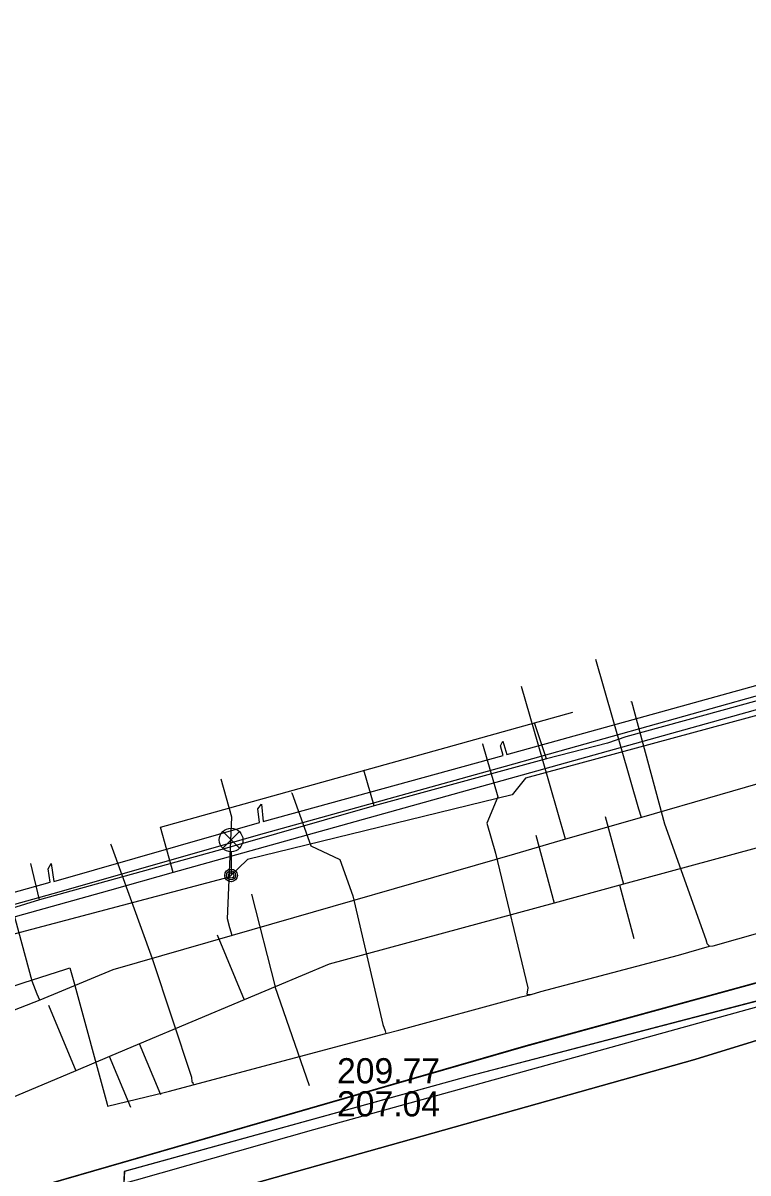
# Model space of a CAD drawing. Extents: x -595540 to -593988, y -1160850 to -1159202.
# Drawn here: x -595477.48 to -595454.45, y -1160206.4 to -1160169.86 of the extents above; entities that cross this region are included whole.
import ezdxf

# ---------------------------------------------------------------- set-up
doc = ezdxf.new("R2010")
doc.units = 0
for name, color, linetype in [('BVK-JEDNOTNA_popisy', 7, 'Continuous'), ('BVK-JEDNOTNA_trasa sítě', 7, 'Continuous'), ('BVK-VODOVOD_trasa sítě', 7, 'Continuous'), ('CETIN_kabel podzemní', 7, 'Continuous'), ('DESTOVA_trasa neprovozované sítě', 7, 'Continuous'), ('DSP-SDEL-VODAFONE_kabel', 7, 'Continuous'), ('EON-NN_kabel', 7, 'Continuous'), ('EON-SDEL_kabel', 7, 'Continuous'), ('INNOGY-STL_trasa sítě', 7, 'Continuous'), ('JEDNOTNA_trasa neprovozované sítě', 7, 'Continuous'), ('QUANTCOM_kabel', 7, 'Continuous'), ('TSB_kabel VO', 7, 'Continuous'), ('TSB_lampy VO', 7, 'Continuous')]:
    doc.layers.add(name, color=color, linetype=linetype)

msp = doc.modelspace()

# ---------------------------------------------------------------- linework, layer by layer
at = {"layer": 'BVK-JEDNOTNA_popisy'}
msp.add_line((-595467.506, -1160203.672), (-595467.506, -1160203.672), dxfattribs=at)
at = {"layer": 'BVK-JEDNOTNA_trasa sítě'}
for points in [[(-595429.502, -1160189.373), (-595434.244, -1160190.66), (-595449.231, -1160194.729), (-595450.1, -1160194.965), (-595458.409, -1160197.221), (-595458.525, -1160197.252), (-595460.609, -1160197.818), (-595467.756, -1160199.758)], [(-595467.756, -1160199.758), (-595469.474, -1160200.481), (-595470.451, -1160200.893), (-595473.778, -1160202.294), (-595474.727, -1160202.693), (-595475.796, -1160203.144), (-595482.321, -1160205.891), (-595489.004, -1160208.705), (-595495.961, -1160211.635), (-595502.779, -1160214.506)]]:
    msp.add_lwpolyline(points, dxfattribs=at)
at = {"layer": 'BVK-VODOVOD_trasa sítě'}
for points in [[(-595433.371, -1160188.474), (-595450.372, -1160192.941), (-595457.841, -1160195.098), (-595460.25, -1160195.793), (-595461.873, -1160196.262), (-595470.837, -1160198.85), (-595474.622, -1160199.943), (-595476.949, -1160200.901), (-595479.453, -1160201.882), (-595489.375, -1160205.387), (-595494.55, -1160207.296), (-595496.292, -1160208.601), (-595507.397, -1160216.918), (-595511.24, -1160217.318)], [(-595457.841, -1160195.098), (-595457.916, -1160194.84), (-595459.291, -1160190.076)], [(-595460.25, -1160195.793), (-595460.985, -1160193.249), (-595461.652, -1160190.937)], [(-595470.837, -1160198.85), (-595470.906, -1160198.611), (-595470.989, -1160198.322), (-595470.847, -1160195.087), (-595471.184, -1160193.884)], [(-595476.949, -1160200.901), (-595477.026, -1160200.714), (-595477.192, -1160200.305), (-595478.434, -1160195.711)]]:
    msp.add_lwpolyline(points, dxfattribs=at)
at = {"layer": 'CETIN_kabel podzemní'}
for points in [[(-595436.82, -1160185.01), (-595436.68, -1160186.27), (-595437.8, -1160187.11), (-595448.91, -1160190.21), (-595472.71, -1160196.85)], [(-595473.11, -1160195.41), (-595460.02, -1160191.75)], [(-595472.71, -1160196.85), (-595473.11, -1160195.41)], [(-595472.71, -1160196.85), (-595474.73, -1160197.42)], [(-595474.73, -1160197.42), (-595503.07, -1160205.33)], [(-595446.81, -1160199.08), (-595468.25, -1160205.02), (-595473.88, -1160206.62), (-595474.28, -1160206.73)], [(-595446.81, -1160199.08), (-595453.59, -1160200.78), (-595463.31, -1160203.32), (-595474.26, -1160206.35), (-595474.28, -1160206.73)]]:
    msp.add_lwpolyline(points, dxfattribs=at)
at = {"layer": 'DESTOVA_trasa neprovozované sítě'}
for p in [(-595470.22, -1160197.54), (-595468.38, -1160203.63)]:
    msp.add_line(p, (-595469.474, -1160200.481), dxfattribs=at)
at = {"layer": 'DSP-SDEL-VODAFONE_kabel'}
for p, q in [((-595449.44, -1160190.1), (-595455.28, -1160191.7)), ((-595455.28, -1160191.7), (-595458.33, -1160192.54)), ((-595460.85, -1160193.24), (-595461.23, -1160192.09)), ((-595458.92, -1160192.74), (-595460.85, -1160193.24)), ((-595458.33, -1160192.54), (-595458.92, -1160192.74)), ((-595460.85, -1160193.24), (-595466.33, -1160194.73)), ((-595466.33, -1160194.73), (-595466.65, -1160193.6)), ((-595466.33, -1160194.73), (-595471.02, -1160196.08)), ((-595471.02, -1160196.08), (-595476.95, -1160197.72)), ((-595476.95, -1160197.72), (-595477.23, -1160196.56)), ((-595476.95, -1160197.72), (-595478.87, -1160198.3))]:
    msp.add_line(p, q, dxfattribs=at)
for points in [[(-595413.104, -1160211.94), (-595415.781, -1160206.019), (-595417.304, -1160202.745), (-595418.846, -1160199.575), (-595420.945, -1160195.335), (-595421.972, -1160193.286), (-595422.732, -1160193.55), (-595430.168, -1160195.953), (-595432.695, -1160196.302), (-595433.235, -1160196.434), (-595433.698, -1160196.516), (-595435.229, -1160196.972), (-595435.74, -1160197.085), (-595436.166, -1160197.235), (-595436.651, -1160197.368), (-595437.606, -1160197.665), (-595450.678, -1160201.105), (-595456.146, -1160202.789), (-595473.119, -1160207.564)], [(-595473.119, -1160207.564), (-595456.146, -1160202.789), (-595450.678, -1160201.105), (-595437.606, -1160197.665), (-595436.651, -1160197.368), (-595436.166, -1160197.235), (-595435.74, -1160197.085), (-595435.229, -1160196.972), (-595433.698, -1160196.516), (-595433.235, -1160196.434), (-595432.695, -1160196.302), (-595430.168, -1160195.953), (-595422.732, -1160193.55)], [(-595473.119, -1160207.564), (-595456.146, -1160202.789), (-595450.678, -1160201.105), (-595437.606, -1160197.665), (-595436.651, -1160197.368), (-595436.166, -1160197.235), (-595435.74, -1160197.085), (-595435.229, -1160196.972), (-595433.698, -1160196.516), (-595433.235, -1160196.434), (-595432.695, -1160196.302), (-595430.168, -1160195.953), (-595422.732, -1160193.55)], [(-595428.8, -1160199.016), (-595429.894, -1160199.431), (-595431.092, -1160198.649), (-595434.259, -1160196.161), (-595435.098, -1160195.864), (-595444.353, -1160198.46), (-595453.588, -1160200.784), (-595463.313, -1160203.317), (-595474.262, -1160206.352), (-595474.287, -1160206.967), (-595473.746, -1160209.094), (-595473.527, -1160213.403), (-595471.041, -1160220.681)]]:
    msp.add_lwpolyline(points, dxfattribs=at)
at = {"layer": 'EON-NN_kabel'}
for points in [[(-595483.257, -1160199.008), (-595476.613, -1160197.16), (-595476.683, -1160196.728), (-595476.586, -1160196.559), (-595476.496, -1160197.133), (-595469.969, -1160195.261), (-595470.017, -1160194.822), (-595469.902, -1160194.676), (-595469.851, -1160195.227), (-595462.231, -1160193.13), (-595462.314, -1160192.819), (-595462.24, -1160192.672), (-595462.116, -1160193.097), (-595451.076, -1160190.039), (-595451.174, -1160189.666), (-595451.094, -1160189.509), (-595450.966, -1160189.991), (-595439.303, -1160186.706), (-595438.814, -1160188.314), (-595436.543, -1160195.46), (-595436.019, -1160197.889), (-595436.002, -1160198.414)], [(-595495.701, -1160250.262), (-595500.278, -1160233.753), (-595501.151, -1160230.603), (-595505.432, -1160214.583), (-595507.104, -1160207.458), (-595506.798, -1160206.888), (-595505.989, -1160206.57), (-595506.055, -1160206.463), (-595505.866, -1160206.422), (-595505.739, -1160206.394), (-595501.343, -1160205.41), (-595500.994, -1160204.257), (-595489.867, -1160201.187), (-595483.299, -1160199.405), (-595476.52, -1160197.518), (-595469.812, -1160195.596), (-595462.151, -1160193.471), (-595450.83, -1160190.291), (-595439.513, -1160187.038), (-595439.111, -1160188.297), (-595436.822, -1160195.513), (-595436.263, -1160198.081), (-595436.2, -1160198.473)]]:
    msp.add_lwpolyline(points, dxfattribs=at)
at = {"layer": 'EON-SDEL_kabel'}
msp.add_lwpolyline([(-595481, -1160207.991), (-595461.51, -1160202.361), (-595440.89, -1160196.711), (-595436.93, -1160185.301), (-595437.35, -1160184.671), (-595437.62, -1160184.061), (-595439.81, -1160179.531), (-595441.07, -1160177.061), (-595441.59, -1160176.011), (-595444.38, -1160170.151), (-595447.98, -1160162.891), (-595448.43, -1160161.911), (-595449.58, -1160159.381), (-595451.65, -1160155.171), (-595452.88, -1160152.441), (-595453.77, -1160150.781)], dxfattribs=at)
at = {"layer": 'INNOGY-STL_trasa sítě'}
for points in [[(-595458.17, -1160191.415), (-595458.158, -1160191.414), (-595457.105, -1160195.307), (-595455.797, -1160198.981), (-595455.767, -1160199.056), (-595455.764, -1160199.099), (-595455.673, -1160199.191)], [(-595462.895, -1160192.761), (-595462.882, -1160192.76), (-595462.395, -1160194.44), (-595462.749, -1160195.286), (-595462.468, -1160196.23), (-595461.444, -1160200.515), (-595461.479, -1160200.713), (-595461.343, -1160200.722)], [(-595468.951, -1160194.318), (-595468.936, -1160194.319), (-595468.341, -1160195.996), (-595467.421, -1160196.433), (-595467.007, -1160197.593), (-595466.049, -1160201.672), (-595465.978, -1160201.883), (-595465.951, -1160201.961)], [(-595474.705, -1160195.941), (-595474.688, -1160195.962), (-595473.374, -1160199.577), (-595472.13, -1160203.352), (-595472.119, -1160203.498), (-595472.089, -1160203.524), (-595472.08, -1160203.591)], [(-595478.261, -1160200.611), (-595477.439, -1160200.347), (-595476.155, -1160199.934), (-595475.987, -1160199.88), (-595475.866, -1160200.325), (-595474.811, -1160204.204), (-595474.794, -1160204.267), (-595472.954, -1160203.826), (-595472.83, -1160203.79), (-595472.08, -1160203.591), (-595465.951, -1160201.961), (-595465.547, -1160201.853), (-595461.661, -1160200.798), (-595461.343, -1160200.722), (-595461.037, -1160200.633), (-595456.66, -1160199.472), (-595455.673, -1160199.191), (-595455.564, -1160199.173), (-595449.93, -1160197.575)]]:
    msp.add_lwpolyline(points, dxfattribs=at)
at = {"layer": 'JEDNOTNA_trasa neprovozované sítě'}
for p, q in [((-595458.994, -1160195.066), (-595458.409, -1160197.221)), ((-595461.194, -1160195.663), (-595460.609, -1160197.818)), ((-595458.07, -1160198.959), (-595458.525, -1160197.252)), ((-595471.309, -1160198.833), (-595470.451, -1160200.893)), ((-595476.664, -1160201.063), (-595475.796, -1160203.144)), ((-595473.105, -1160203.913), (-595473.778, -1160202.294)), ((-595474.054, -1160204.309), (-595474.727, -1160202.693))]:
    msp.add_line(p, q, dxfattribs=at)
at = {"layer": 'QUANTCOM_kabel'}
msp.add_lwpolyline([(-595442.68, -1160197.34), (-595442.897, -1160197.26), (-595461.51, -1160202.36), (-595481, -1160207.99), (-595496.95, -1160212.31)], dxfattribs=at)
at = {"layer": 'TSB_kabel VO'}
msp.add_lwpolyline([(-595429.24, -1160179.51), (-595428.28, -1160180.77), (-595426.55, -1160183.37), (-595438.36, -1160187.37), (-595439.02, -1160188.22), (-595439.62, -1160187.73), (-595448.59, -1160190.35), (-595461.52, -1160193.85), (-595461.94, -1160194.38), (-595470.35, -1160196.43), (-595470.93, -1160197), (-595497.45, -1160204.02), (-595497.73, -1160204.67), (-595498.11, -1160204.37), (-595506.86, -1160206.52), (-595508.22, -1160206.5), (-595505.94, -1160214.71), (-595504.46, -1160214.78), (-595504.75, -1160218.47), (-595502.35, -1160228.99), (-595497.65, -1160230.7)], dxfattribs=at)
at = {"layer": 'TSB_lampy VO'}
for p, q in [((-595471.135, -1160196.08), (-595470.605, -1160195.55)), ((-595471.135, -1160195.55), (-595470.605, -1160196.08)), ((-595471.135, -1160196.08), (-595470.605, -1160195.55)), ((-595471.135, -1160195.55), (-595470.605, -1160196.08)), ((-595470.87, -1160196.19), (-595470.87, -1160196.94)), ((-595470.87, -1160196.19), (-595470.87, -1160196.94))]:
    msp.add_line(p, q, dxfattribs=at)
for centre, radius in [((-595470.87, -1160195.815), 0.375), ((-595470.87, -1160195.815), 0.375), ((-595470.87, -1160196.94), 0.2), ((-595470.87, -1160196.94), 0.2), ((-595470.87, -1160196.94), 0.145), ((-595470.87, -1160196.94), 0.145), ((-595470.87, -1160196.94), 0.0876), ((-595470.87, -1160196.94), 0.0876)]:
    msp.add_circle(centre, radius, dxfattribs=at)

# ---------------------------------------------------------------- texts
at = {"layer": 'BVK-JEDNOTNA_popisy'}
for s, p in [('209.77', (-595467.506, -1160203.547)), ('207.04', (-595467.506, -1160204.597))]:
    msp.add_text(s, height=0.8, dxfattribs=at).set_placement(p)

doc.saveas('drawing.dxf')
